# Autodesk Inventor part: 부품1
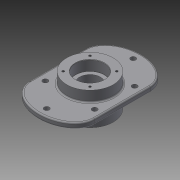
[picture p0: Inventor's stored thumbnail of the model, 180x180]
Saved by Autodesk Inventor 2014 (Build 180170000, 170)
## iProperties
Created: 2015-02
Part Number: 부품1
Material: 일반
Document SubType Name: Modeling
Designer: basic
Density: 1 g/cm^3
Appearance: 기본값
Author: basic
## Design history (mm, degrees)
sketch "스케치1"
  geometry: L1 (70, 60)-(70, -60); L2 (-70, -60)-(-70, 60); L3 (0, 0)-(0, 18.209); L4 (0, 0)-(18.955, 0); 3 further points; 2 other entities
  constraints: 8 end point, 3 point on line, 2 parallel, 1 perpendicular, 10 other
  dimensions: "d0" = 120 distance of L1.start L1.end; "d1" = 140 distance of L2.end L1.start
extrude "돌출1" new body sketch "스케치1" distance "d4" = 12; taper "d5" = 0 deg
node "작업 평면1"
sketch "스케치2"
  geometry: C1 r 50 at (0, 0); 1 further point
  constraints: 1 centre point, 1 coincident
  dimensions: "d7" = 100 diameter of C1
extrude "돌출2" join sketch "스케치2" distance "d8" = 70; taper "d9" = 0 deg
hole "구멍1" diameter "d12" = 62; stored, may be unused: countersink angle "d16" = 45 deg, drill point angle "d18" = 0 deg; dims "d10" = 10, "d11" = 10, "d13" = 6, "d14" = 63, "d15" = 2, "d17" = 22
hole "구멍2" diameter "d21" = 62; stored, may be unused: countersink angle "d25" = 45 deg, drill point angle "d27" = 0 deg; dims "d19" = 10, "d20" = 10, "d22" = 6, "d23" = 63, "d24" = 2, "d26" = 22
hole "구멍3" diameter "d30" = 45; stored, may be unused: countersink angle "d34" = 45 deg, drill point angle "d36" = 0 deg; dims "d28" = 10, "d29" = 10, "d31" = 6, "d32" = 63, "d33" = 2, "d35" = 22
sketch "스케치3"
  geometry: L1 (-70, -60)-(-70, 60) reference; L2 (70, 60)-(70, -60) reference; L3 (-53, -59.974)-(-53, 60); L4 (53, 60)-(53, -60.026); L5 (0, 0)-(0, 15.789); L6 (0, 0)-(13.967, 0); C1 r 50 at (0, 0) reference; C2 r 10 at (0, 93); C3 r 10 at (53, 43); C4 r 10 at (-53, 43); C5 r 10 at (0, -93); C6 r 10 at (53, -43); C7 r 10 at (-53, -43); 2 further points; 2 other entities
  constraints: 8 end point, 6 centre point, 4 parallel, 4 symmetric about line, 2 point on line, 1 perpendicular, 13 other
  dimensions: "d37" = 17 distance between parallel lines of L2 L4; "d38" = 20 diameter of C2; "d39" = 20 diameter of C3; "d95" = 86 distance of C6.centre C3.centre
extrude "돌출3" join sketch "스케치3" distance "d40" = 5; taper "d41" = 0 deg
hole "구멍4" diameter "d44" = 11; stored, may be unused: countersink angle "d48" = 45 deg, drill point angle "d50" = 0 deg; dims "d42" = 10, "d43" = 10, "d45" = 6, "d46" = 63, "d47" = 2, "d49" = 22
hole "구멍5" diameter "d53" = 11; stored, may be unused: countersink angle "d57" = 45 deg, drill point angle "d59" = 0 deg; dims "d51" = 10, "d52" = 10, "d54" = 6, "d55" = 63, "d56" = 2, "d58" = 22
hole "구멍6" diameter "d62" = 11; stored, may be unused: countersink angle "d66" = 45 deg, drill point angle "d68" = 0 deg; dims "d60" = 10, "d61" = 10, "d63" = 6, "d64" = 63, "d65" = 2, "d67" = 22
sketch "스케치4"
  geometry: L1 (0, 0)-(0, 60.727); L2 (0, 0)-(-61.739, 0); L3 (0, 0)-(-38.749, 38.749); L4 (0, 0)-(61.739, 0); L5 (0, 0)-(-30.87, -30.87); L6 (0, 0)-(28.815, 28.815); L7 (0, 0)-(28.815, -28.815); C1 r 50 at (0, 0) reference; A1 r 40.75 centre (0, 0) between (-28.815, 28.815) and (28.815, 28.815); 3 further points
  constraints: 14 end point, 4 point on circle, 3 coincident, 3 perpendicular, 2 point on line, 1 centre point, 1 collinear, 1 symmetric about line, 1 vertical
  dimensions: "d69" = 9.25 radial gap between concentric circles of C1 A1; "d70" = 45 deg angle of L2 L3
hole "구멍7" sketch "스케치4" at (-28.815, 28.815), (28.815, 28.815), (28.815, -28.815), (-28.815, -28.815) diameter "d71" = 4.917; stored, may be unused: countersink angle "d75" = 45 deg, drill point angle "d77" = 118 deg; dims "d72" = 10, "d73" = 63, "d74" = 2, "d76" = 13
sketch "스케치5"
  geometry: L1 (28.815, 28.815)-(0, 0); L2 (0, 0)-(-28.815, -28.815); L3 (-28.815, 28.815)-(0, 0); L4 (0, 0)-(22.274, -22.274); L5 (-40.75, 0)-(40.75, 0); L6 (22.274, -22.274)-(28.815, -28.815); C1 r 50 at (0, 0) reference; 5 further points
  constraints: 12 end point, 3 coincident, 3 collinear, 1 horizontal, 12 other
  dimensions: "d78" = 9.25 dimension on C1; "d79" = 45 deg angle of L5 L3; "d80" = 45 deg angle of L5 L2
hole "구멍8" sketch "스케치5" at (-28.815, 28.815), (28.815, 28.815), (28.815, -28.815), (-28.815, -28.815) diameter "d81" = 4.917; stored, may be unused: countersink angle "d85" = 45 deg, drill point angle "d87" = 118 deg; dims "d82" = 10, "d83" = 63, "d84" = 2, "d86" = 13
fillet "모깎기1" dims "d88" = 3
sketch "스케치6"
  geometry: L1 (-32.916, 73.481)-(32.916, 73.481); L2 (32.916, 73.481)-(32.916, 56.519); L3 (32.916, 56.519)-(-32.916, 56.519); L4 (-32.916, 56.519)-(-32.916, 73.481); L5 (0, 73.481)-(0, 56.519); L6 (32.916, 65)-(-32.916, 65); L7 (0, 0)-(0, 16.535); L8 (5.038, 0)-(19.577, 0); C1 r 53 at (0, 0) reference
  constraints: 8 end point, 4 midpoint, 2 perpendicular, 1 collinear, 2 other
  dimensions: "d92" = 65 distance between parallel lines of L8 L6
extrude "돌출4" join sketch "스케치6" distance "d93" = 1; taper "d94" = 0 deg
fillet "모깎기2" dims "d96" = 0.3
node "솔리드1"
mirror "대칭1"
other parameters: "d6" = 23
